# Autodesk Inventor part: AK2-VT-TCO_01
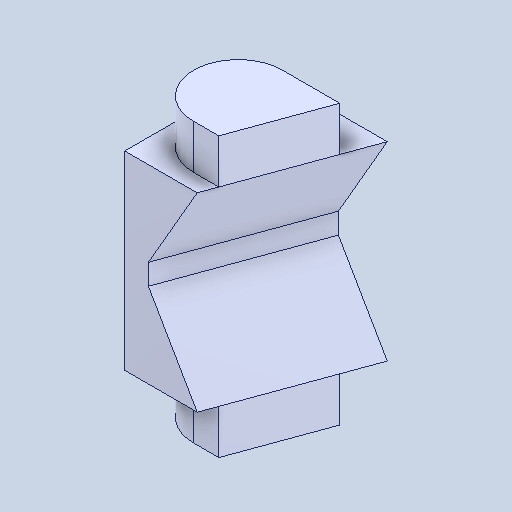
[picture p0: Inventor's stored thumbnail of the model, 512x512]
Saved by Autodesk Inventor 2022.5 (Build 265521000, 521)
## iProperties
Created: 2024-07
Part Number: AK2-VT-TCO_01
Material: 一般
Document SubType Name: Modeling
Designer: ImaoCorp
Density: 1 g/cm^3
Appearance: 既定
Author: ImaoCorp
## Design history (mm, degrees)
feature "AK2-VT-TCO_01"
node "ソリッド1"
